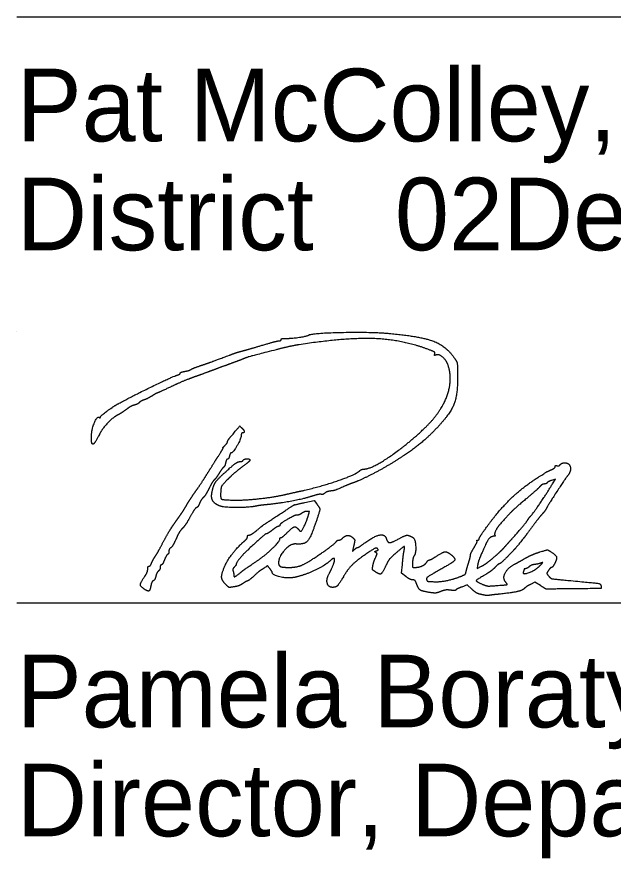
# Model space of a CAD drawing. Extents: x 36.7 to 70.7, y 0 to 22.
# Drawn here: x 61.221 to 62.37, y 7.302 to 8.923 of the extents above; entities that cross this region are included whole.
import ezdxf

# ---------------------------------------------------------------- set-up
doc = ezdxf.new("R2010")
doc.units = 0
for name, color, linetype in [('Default', 7, 'Continuous'), ('SH_Data', 7, 'Continuous'), ('SH_Text', 7, 'Continuous')]:
    doc.layers.add(name, color=color, linetype=linetype)

msp = doc.modelspace()

# ---------------------------------------------------------------- linework, layer by layer
at = {"layer": 'Default'}
for points in [[(62.2531, 8.0232), (62.2585, 8.0321), (62.2511, 8.0296)], [(61.7758, 7.987), (61.7938, 7.9911), (61.7985, 7.9849)], [(61.9707, 7.8442), (61.9624, 7.8506), (61.9639, 7.8676)], [(62.1087, 7.8662), (62.1077, 7.8597), (62.1163, 7.8642)], [(62.2296, 7.8269), (62.2189, 7.8337), (62.2105, 7.8292)], [(62.0977, 7.8199), (62.0885, 7.8282), (62.078, 7.8241)]]:
    msp.add_lwpolyline(points, dxfattribs=at)
for points in [[(61.7302, 8.3012), (61.7302, 8.3025), (61.7342, 8.3035), (61.7392, 8.3034)], [(61.7392, 8.3034), (61.7488, 8.3031), (61.7798, 8.3075), (61.7832, 8.3096)], [(62.0139, 8.282), (61.9633, 8.301), (61.8553, 8.3049), (61.765, 8.2912)], [(61.7832, 8.3096), (61.79, 8.3138), (61.907, 8.3161), (61.9414, 8.3127)], [(61.9414, 8.3127), (62.0007, 8.3069), (62.0482, 8.2886), (62.064, 8.2655)], [(61.6546, 8.2789), (61.6599, 8.2802), (61.6774, 8.2853), (61.6934, 8.29)], [(61.6934, 8.29), (61.7095, 8.2948), (61.7244, 8.2987), (61.7264, 8.2987)], [(61.765, 8.2912), (61.7558, 8.2898), (61.7358, 8.2854), (61.7206, 8.2815)], [(61.7264, 8.2987), (61.7285, 8.2987), (61.7302, 8.2998), (61.7302, 8.3012)], [(61.5742, 8.2505), (61.5889, 8.2555), (61.5954, 8.2579), (61.6306, 8.271)], [(61.6306, 8.271), (61.6385, 8.274), (61.6493, 8.2775), (61.6546, 8.2789)], [(61.7206, 8.2815), (61.6696, 8.2683), (61.6653, 8.267), (61.6546, 8.2627)], [(62.0262, 8.2733), (62.0272, 8.2758), (62.0237, 8.2783), (62.0139, 8.282)], [(62.0286, 8.2713), (62.026, 8.2703), (62.0253, 8.2709), (62.0262, 8.2733)], [(62.052, 8.2513), (62.0487, 8.2611), (62.0343, 8.2734), (62.0286, 8.2713)], [(61.6318, 8.2542), (61.6219, 8.2506), (61.6068, 8.245), (61.5982, 8.2418)], [(61.6546, 8.2627), (61.652, 8.2616), (61.6417, 8.2578), (61.6318, 8.2542)], [(62.064, 8.2655), (62.0689, 8.2583), (62.0698, 8.2539), (62.0702, 8.2361)], [(61.5358, 8.2362), (61.5358, 8.2373), (61.5398, 8.2389), (61.5448, 8.2398)], [(61.5448, 8.2398), (61.5497, 8.2407), (61.5549, 8.2423), (61.5562, 8.2433)], [(61.5562, 8.2433), (61.5575, 8.2443), (61.5656, 8.2475), (61.5742, 8.2505)], [(61.5982, 8.2418), (61.5896, 8.2386), (61.5734, 8.2326), (61.5622, 8.2287)], [(62.0065, 8.1302), (62.0374, 8.1596), (62.0613, 8.2231), (62.052, 8.2513)], [(61.4182, 8.1783), (61.4484, 8.1945), (61.522, 8.2302), (61.5304, 8.2326)], [(61.5622, 8.2287), (61.551, 8.2247), (61.5306, 8.2161), (61.517, 8.2096)], [(61.5304, 8.2326), (61.5334, 8.2335), (61.5358, 8.2351), (61.5358, 8.2362)], [(62.0702, 8.2361), (62.0709, 8.1953), (62.0548, 8.1556), (62.0254, 8.1257)], [(61.517, 8.2096), (61.5033, 8.2032), (61.4917, 8.1979), (61.4911, 8.1979)], [(61.4811, 8.1922), (61.4762, 8.1891), (61.4695, 8.1857), (61.4663, 8.1847)], [(61.4911, 8.1979), (61.4906, 8.1979), (61.4861, 8.1953), (61.4811, 8.1922)], [(61.3822, 8.1517), (61.3822, 8.1538), (61.4076, 8.1726), (61.4182, 8.1783)], [(61.4474, 8.1747), (61.4439, 8.1739), (61.4372, 8.1702), (61.4326, 8.1666)], [(61.4571, 8.1796), (61.4553, 8.1778), (61.451, 8.1756), (61.4474, 8.1747)], [(61.4663, 8.1847), (61.4631, 8.1837), (61.4589, 8.1814), (61.4571, 8.1796)], [(61.4326, 8.1666), (61.428, 8.1631), (61.4208, 8.1584), (61.4167, 8.1563)], [(61.365, 8.1138), (61.3651, 8.127), (61.3758, 8.1536), (61.3799, 8.151)], [(61.3799, 8.151), (61.3812, 8.1502), (61.3822, 8.1505), (61.3822, 8.1517)], [(61.4167, 8.1563), (61.4063, 8.151), (61.3864, 8.1301), (61.3802, 8.118)], [(61.6324, 8.1127), (61.6509, 8.1349), (61.6502, 8.1343), (61.6543, 8.1309)], [(61.6543, 8.1309), (61.6586, 8.1273), (61.6595, 8.1211), (61.6558, 8.1211)], [(61.8898, 8.0515), (61.9039, 8.0515), (61.972, 8.0974), (62.0065, 8.1302)], [(62.0254, 8.1257), (62.0068, 8.1068), (61.9744, 8.0819), (61.9439, 8.0631)], [(61.3664, 8.1001), (61.3656, 8.1009), (61.365, 8.107), (61.365, 8.1138)], [(61.3802, 8.118), (61.3735, 8.1051), (61.3682, 8.0982), (61.3664, 8.1001)], [(61.627, 8.1041), (61.627, 8.1053), (61.6294, 8.1092), (61.6324, 8.1127)], [(61.6534, 8.116), (61.6534, 8.1104), (61.6375, 8.0827), (61.6343, 8.0827)], [(61.6558, 8.1211), (61.6545, 8.1211), (61.6534, 8.1188), (61.6534, 8.116)], [(61.6094, 8.0766), (61.615, 8.0852), (61.619, 8.0923), (61.6184, 8.0923)], [(61.6184, 8.0923), (61.6179, 8.0923), (61.6196, 8.0944), (61.6222, 8.0971)], [(61.6222, 8.0971), (61.6248, 8.0997), (61.627, 8.1029), (61.627, 8.1041)], [(61.5874, 8.0416), (61.594, 8.0522), (61.6039, 8.068), (61.6094, 8.0766)], [(61.6308, 8.0767), (61.63, 8.0734), (61.6283, 8.0707), (61.6271, 8.0707)], [(61.6343, 8.0827), (61.6332, 8.0827), (61.6316, 8.08), (61.6308, 8.0767)], [(61.6186, 8.0417), (61.6343, 8.0563), (61.6471, 8.0659), (61.651, 8.0659)], [(61.6234, 8.0635), (61.6225, 8.0596), (61.6208, 8.0557), (61.6195, 8.0549)], [(61.6271, 8.0707), (61.6259, 8.0707), (61.6243, 8.0674), (61.6234, 8.0635)], [(61.651, 8.0659), (61.6535, 8.0659), (61.6562, 8.067), (61.657, 8.0683)], [(61.6702, 8.0686), (61.6702, 8.0675), (61.6634, 8.0616), (61.6552, 8.0555)], [(61.657, 8.0683), (61.6588, 8.0712), (61.6702, 8.0715), (61.6702, 8.0686)], [(61.9439, 8.0631), (61.9247, 8.0512), (61.8835, 8.0302), (61.8694, 8.0251)], [(62.2616, 8.0579), (62.2635, 8.0571), (62.2663, 8.0581), (62.2679, 8.06)], [(62.2679, 8.06), (62.2695, 8.0619), (62.2732, 8.0635), (62.2761, 8.0635)], [(62.2761, 8.0635), (62.2856, 8.0635), (62.2893, 8.0474), (62.2819, 8.0385)], [(61.611, 8.0435), (61.6076, 8.038), (61.6035, 8.0324), (61.6019, 8.031)], [(61.6195, 8.0549), (61.6182, 8.0541), (61.6144, 8.049), (61.611, 8.0435)], [(61.6552, 8.0555), (61.6469, 8.0494), (61.6344, 8.0386), (61.6274, 8.0314)], [(61.7698, 8.0095), (61.8067, 8.0177), (61.873, 8.0406), (61.8816, 8.0482)], [(61.8816, 8.0482), (61.8837, 8.05), (61.8874, 8.0515), (61.8898, 8.0515)], [(62.2214, 8.0331), (62.2404, 8.0453), (62.2422, 8.0464), (62.2504, 8.0501)], [(62.2504, 8.0501), (62.2547, 8.052), (62.2582, 8.0549), (62.2582, 8.0564)], [(62.2582, 8.0564), (62.2582, 8.0579), (62.2597, 8.0586), (62.2616, 8.0579)], [(61.5656, 8.0087), (61.571, 8.0161), (61.5808, 8.031), (61.5874, 8.0416)], [(61.6019, 8.031), (61.6002, 8.0297), (61.5955, 8.0221), (61.5915, 8.0141)], [(61.5973, 8.0071), (61.6, 8.0201), (61.6062, 8.0301), (61.6186, 8.0417)], [(61.6274, 8.0314), (61.6167, 8.0204), (61.6145, 8.0168), (61.614, 8.0085)], [(62.1268, 7.9406), (62.1491, 7.9714), (62.1941, 8.0154), (62.2214, 8.0331)], [(62.2819, 8.0385), (62.2777, 8.0334), (62.2449, 7.983), (62.2417, 7.9768)], [(62.2511, 8.0296), (62.2471, 8.0282), (62.2432, 8.026), (62.2424, 8.0248)], [(61.5915, 8.0141), (61.5875, 8.0061), (61.5824, 7.9981), (61.5802, 7.9963)], [(61.8538, 8.0189), (61.8367, 8.0115), (61.8318, 8.0098), (61.8252, 8.0091)], [(61.8694, 8.0251), (61.8648, 8.0235), (61.8577, 8.0207), (61.8538, 8.0189)], [(62.2283, 8.0173), (62.2256, 8.0143), (62.2131, 8.0032), (62.2006, 7.9927)], [(62.2103, 7.9603), (62.2131, 7.9622), (62.2413, 8.0037), (62.2531, 8.0232)], [(62.2371, 8.0227), (62.2349, 8.0227), (62.2309, 8.0202), (62.2283, 8.0173)], [(62.2424, 8.0248), (62.2417, 8.0236), (62.2393, 8.0227), (62.2371, 8.0227)], [(61.5489, 7.9831), (61.5528, 7.9897), (61.5603, 8.0012), (61.5656, 8.0087)], [(61.5802, 7.9963), (61.5781, 7.9945), (61.5748, 7.9895), (61.573, 7.9851)], [(61.6126, 7.9802), (61.6021, 7.9841), (61.595, 7.9966), (61.5973, 8.0071)], [(61.614, 8.0085), (61.6131, 7.9951), (61.6172, 7.9922), (61.6378, 7.9917)], [(61.6378, 7.9917), (61.657, 7.9911), (61.7149, 7.9972), (61.7362, 8.002)], [(61.7896, 7.9991), (61.7731, 7.9938), (61.728, 7.9853), (61.7042, 7.983)], [(61.7362, 8.002), (61.7441, 8.0038), (61.7592, 8.0072), (61.7698, 8.0095)], [(61.8076, 8.0028), (61.8059, 8.0034), (61.7978, 8.0017), (61.7896, 7.9991)], [(61.8144, 8.005), (61.8123, 8.0032), (61.8092, 8.0022), (61.8076, 8.0028)], [(61.8252, 8.0091), (61.8213, 8.0086), (61.8165, 8.0068), (61.8144, 8.005)], [(61.5359, 7.9624), (61.5392, 7.9672), (61.5451, 7.9765), (61.5489, 7.9831)], [(61.573, 7.9851), (61.5711, 7.9807), (61.5686, 7.9771), (61.5673, 7.9771)], [(61.6838, 7.9804), (61.6701, 7.9773), (61.6206, 7.9772), (61.6126, 7.9802)], [(61.7042, 7.983), (61.6959, 7.9822), (61.6867, 7.981), (61.6838, 7.9804)], [(61.7218, 7.9606), (61.7534, 7.9816), (61.7548, 7.9823), (61.7758, 7.987)], [(61.7985, 7.9849), (61.8051, 7.9762), (61.8049, 7.9713), (61.7972, 7.9487)], [(62.2006, 7.9927), (62.181, 7.9762), (62.1693, 7.9648), (62.1526, 7.9459)], [(61.5223, 7.9432), (61.5264, 7.949), (61.5325, 7.9577), (61.5359, 7.9624)], [(61.5673, 7.9771), (61.566, 7.9771), (61.5606, 7.9692), (61.5552, 7.9595)], [(61.7612, 7.9627), (61.759, 7.9627), (61.7546, 7.9613), (61.7515, 7.9595)], [(61.7699, 7.9662), (61.7674, 7.9643), (61.7634, 7.9627), (61.7612, 7.9627)], [(61.7684, 7.9315), (61.7702, 7.9315), (61.78, 7.9526), (61.7831, 7.9633)], [(61.7798, 7.9698), (61.7769, 7.9698), (61.7725, 7.9681), (61.7699, 7.9662)], [(61.7831, 7.9633), (61.7848, 7.9691), (61.7844, 7.9699), (61.7798, 7.9698)], [(62.2331, 7.9647), (62.2301, 7.9614), (62.2212, 7.9501), (62.2133, 7.9395)], [(62.2417, 7.9768), (62.24, 7.9733), (62.2361, 7.9679), (62.2331, 7.9647)], [(61.5552, 7.9595), (61.5499, 7.9499), (61.5432, 7.9399), (61.5404, 7.9373)], [(61.6826, 7.9327), (61.6963, 7.9438), (61.6943, 7.9424), (61.7218, 7.9606)], [(61.7515, 7.9595), (61.7371, 7.9516), (61.7278, 7.9452), (61.7278, 7.9432)], [(61.7972, 7.9487), (61.7869, 7.9188), (61.775, 7.9058), (61.759, 7.9071)], [(62.1751, 7.9173), (62.1904, 7.9344), (62.204, 7.9508), (62.2064, 7.9551)], [(62.2064, 7.9551), (62.2076, 7.9573), (62.2094, 7.9596), (62.2103, 7.9603)], [(61.5034, 7.9111), (61.5097, 7.923), (61.5182, 7.9374), (61.5223, 7.9432)], [(61.5404, 7.9373), (61.5375, 7.9348), (61.532, 7.9257), (61.5281, 7.9171)], [(61.6688, 7.9243), (61.6706, 7.9243), (61.6768, 7.9281), (61.6826, 7.9327)], [(61.7134, 7.9339), (61.7084, 7.9299), (61.7034, 7.9267), (61.7022, 7.9267)], [(61.7251, 7.9411), (61.7237, 7.9411), (61.7184, 7.9378), (61.7134, 7.9339)], [(61.7278, 7.9432), (61.7278, 7.942), (61.7266, 7.9411), (61.7251, 7.9411)], [(61.7422, 7.9291), (61.7523, 7.9392), (61.7589, 7.941), (61.7638, 7.9351)], [(61.7638, 7.9351), (61.7654, 7.9331), (61.7675, 7.9315), (61.7684, 7.9315)], [(62.1118, 7.9172), (62.1118, 7.9187), (62.1185, 7.9292), (62.1268, 7.9406)], [(62.1526, 7.9459), (62.1467, 7.9393), (62.1405, 7.9264), (62.1419, 7.9241)], [(62.2133, 7.9395), (62.2054, 7.9288), (62.1978, 7.9186), (62.1963, 7.9168)], [(61.5281, 7.9171), (61.5241, 7.9085), (61.5194, 7.9006), (61.5176, 7.8996)], [(61.66, 7.913), (61.6629, 7.9155), (61.6654, 7.919), (61.6654, 7.9208)], [(61.6654, 7.9208), (61.6654, 7.9227), (61.6669, 7.9243), (61.6688, 7.9243)], [(61.7022, 7.9267), (61.7004, 7.9266), (61.6919, 7.9194), (61.6666, 7.8961)], [(61.6817, 7.8729), (61.6973, 7.8833), (61.7278, 7.9121), (61.7278, 7.9163)], [(61.7278, 7.9163), (61.7278, 7.9181), (61.7289, 7.9195), (61.7302, 7.9195)], [(61.7302, 7.9195), (61.7315, 7.9195), (61.7369, 7.9238), (61.7422, 7.9291)], [(61.8365, 7.9116), (61.8376, 7.9133), (61.8399, 7.9147), (61.8417, 7.9147)], [(61.8417, 7.9147), (61.8436, 7.9147), (61.8468, 7.9164), (61.8489, 7.9186)], [(61.8489, 7.9186), (61.8539, 7.9235), (61.8639, 7.9236), (61.8688, 7.9187)], [(61.8688, 7.9187), (61.872, 7.9155), (61.8722, 7.913), (61.8701, 7.9039)], [(61.887, 7.906), (61.9072, 7.9212), (61.9299, 7.9268), (61.9329, 7.9173)], [(61.9329, 7.9173), (61.9353, 7.9097), (61.9434, 7.9096), (61.9567, 7.917)], [(61.9567, 7.917), (61.9686, 7.9236), (61.9759, 7.9243), (61.9841, 7.9197)], [(61.9841, 7.9197), (61.9885, 7.9173), (61.9902, 7.8892), (61.9863, 7.8841)], [(62.1076, 7.9132), (62.1068, 7.914), (62.1075, 7.9147), (62.109, 7.9147)], [(62.109, 7.9147), (62.1105, 7.9147), (62.1118, 7.9158), (62.1118, 7.9172)], [(62.1397, 7.9219), (62.1333, 7.9219), (62.1238, 7.9067), (62.1117, 7.8775)], [(62.1419, 7.9241), (62.1427, 7.9229), (62.1416, 7.9219), (62.1397, 7.9219)], [(62.1595, 7.8998), (62.1626, 7.9034), (62.1696, 7.9112), (62.1751, 7.9173)], [(62.1963, 7.9168), (62.183, 7.9004), (62.1785, 7.8952), (62.1666, 7.883)], [(61.488, 7.8835), (61.4902, 7.8868), (61.4972, 7.8992), (61.5034, 7.9111)], [(61.5176, 7.8996), (61.5157, 7.8985), (61.5142, 7.8956), (61.5142, 7.8931)], [(61.6219, 7.8648), (61.6264, 7.8753), (61.6496, 7.9047), (61.66, 7.913)], [(61.759, 7.9071), (61.7486, 7.908), (61.7254, 7.8826), (61.7254, 7.8704)], [(61.7938, 7.8798), (61.8124, 7.8922), (61.8348, 7.9088), (61.8365, 7.9116)], [(61.8701, 7.9039), (61.8678, 7.8936), (61.8679, 7.8931), (61.8717, 7.8966)], [(61.8717, 7.8966), (61.8739, 7.8986), (61.8766, 7.9003), (61.8775, 7.9003)], [(61.8775, 7.9003), (61.8785, 7.9003), (61.8827, 7.9028), (61.887, 7.906)], [(61.9156, 7.8982), (61.9138, 7.9), (61.9079, 7.8972), (61.8954, 7.8887)], [(61.914, 7.894), (61.917, 7.8952), (61.9174, 7.8964), (61.9156, 7.8982)], [(61.9668, 7.8925), (61.9687, 7.9019), (61.966, 7.9023), (61.9567, 7.8941)], [(62.095, 7.8856), (62.095, 7.8874), (62.0982, 7.8941), (62.102, 7.9004)], [(62.102, 7.9004), (62.1059, 7.9067), (62.1084, 7.9125), (62.1076, 7.9132)], [(62.1394, 7.881), (62.1473, 7.8878), (62.1564, 7.8963), (62.1595, 7.8998)], [(61.4811, 7.8709), (61.4827, 7.8745), (61.4858, 7.8802), (61.488, 7.8835)], [(61.5117, 7.887), (61.5103, 7.8862), (61.5075, 7.8812), (61.5054, 7.8761)], [(61.5142, 7.8931), (61.5142, 7.8906), (61.5131, 7.8879), (61.5117, 7.887)], [(61.6666, 7.8961), (61.6575, 7.8878), (61.6438, 7.8707), (61.6438, 7.8677)], [(61.8954, 7.8887), (61.8757, 7.8753), (61.8585, 7.8583), (61.8502, 7.8439)], [(61.9128, 7.8906), (61.9106, 7.8919), (61.9109, 7.8928), (61.914, 7.894)], [(61.9121, 7.8807), (61.915, 7.887), (61.9151, 7.8891), (61.9128, 7.8906)], [(61.9567, 7.8941), (61.9408, 7.8801), (61.9371, 7.8757), (61.9316, 7.8643)], [(61.9639, 7.8676), (61.9647, 7.877), (61.966, 7.8882), (61.9668, 7.8925)], [(61.9863, 7.8841), (61.985, 7.8824), (61.9837, 7.8767), (61.9833, 7.8715)], [(62.0158, 7.8763), (62.017, 7.8763), (62.0231, 7.8795), (62.0294, 7.8835)], [(62.0576, 7.8864), (62.0673, 7.8788), (62.0604, 7.8709), (62.0289, 7.8532)], [(62.0294, 7.8835), (62.0423, 7.8917), (62.0499, 7.8925), (62.0576, 7.8864)], [(62.0915, 7.8715), (62.0934, 7.8774), (62.095, 7.8838), (62.095, 7.8856)], [(62.1666, 7.883), (62.1591, 7.8754), (62.1521, 7.8691), (62.151, 7.8691)], [(62.1994, 7.879), (62.2073, 7.8835), (62.2205, 7.8892), (62.2287, 7.8917)], [(62.2287, 7.8917), (62.2427, 7.8959), (62.2439, 7.8959), (62.2498, 7.8921)], [(62.2498, 7.8921), (62.2594, 7.8858), (62.2618, 7.8784), (62.2572, 7.8694)], [(61.4758, 7.8643), (61.4772, 7.8643), (61.4796, 7.8672), (61.4811, 7.8709)], [(61.4995, 7.8667), (61.4984, 7.8667), (61.4974, 7.8646), (61.4974, 7.8622)], [(61.5054, 7.8761), (61.5034, 7.8709), (61.5007, 7.8667), (61.4995, 7.8667)], [(61.6438, 7.8677), (61.6438, 7.867), (61.6421, 7.8646), (61.6401, 7.8626)], [(61.6502, 7.8506), (61.6577, 7.8567), (61.663, 7.8604), (61.6817, 7.8729)], [(61.7088, 7.8593), (61.7043, 7.8651), (61.7043, 7.8651), (61.6975, 7.8607)], [(61.7254, 7.8704), (61.7254, 7.8652), (61.7332, 7.8619), (61.7453, 7.8619)], [(61.7453, 7.8619), (61.7584, 7.8619), (61.7775, 7.8689), (61.7938, 7.8798)], [(61.8258, 7.8756), (61.8162, 7.8665), (61.7774, 7.8477), (61.759, 7.8433)], [(61.8228, 7.8499), (61.8269, 7.8575), (61.8334, 7.8738), (61.8334, 7.8766)], [(61.8334, 7.8766), (61.8334, 7.8796), (61.8294, 7.8791), (61.8258, 7.8756)], [(61.9116, 7.8536), (61.9066, 7.8568), (61.9058, 7.8588), (61.907, 7.8651)], [(61.907, 7.8651), (61.9078, 7.8693), (61.9101, 7.8763), (61.9121, 7.8807)], [(61.9833, 7.8715), (61.9828, 7.8639), (61.9835, 7.8619), (61.9867, 7.8619)], [(61.9867, 7.8619), (61.995, 7.8619), (62.007, 7.8667), (62.0102, 7.8714)], [(62.0102, 7.8714), (62.0121, 7.8741), (62.0146, 7.8763), (62.0158, 7.8763)], [(62.0867, 7.8544), (62.0874, 7.8579), (62.0896, 7.8655), (62.0915, 7.8715)], [(62.1117, 7.8775), (62.1106, 7.8748), (62.1093, 7.8698), (62.1087, 7.8662)], [(62.1163, 7.8642), (62.1211, 7.8666), (62.1315, 7.8742), (62.1394, 7.881)], [(62.151, 7.8691), (62.1499, 7.8691), (62.146, 7.8659), (62.1424, 7.8621)], [(62.1628, 7.8336), (62.1567, 7.841), (62.1665, 7.8608), (62.1798, 7.868)], [(62.1798, 7.868), (62.1827, 7.8695), (62.1915, 7.8745), (62.1994, 7.879)], [(62.2188, 7.8676), (62.2149, 7.8671), (62.21, 7.8651), (62.2078, 7.8631)], [(62.2306, 7.8703), (62.228, 7.8693), (62.2226, 7.8681), (62.2188, 7.8676)], [(62.2282, 7.8648), (62.2337, 7.8704), (62.2343, 7.8717), (62.2306, 7.8703)], [(62.2572, 7.8694), (62.255, 7.8653), (62.2523, 7.8619), (62.2512, 7.8619)], [(61.4676, 7.8444), (61.4708, 7.8491), (61.4734, 7.8555), (61.4734, 7.8586)], [(61.4734, 7.8586), (61.4734, 7.8617), (61.4745, 7.8643), (61.4758, 7.8643)], [(61.4939, 7.8548), (61.4921, 7.8532), (61.4898, 7.8487), (61.4889, 7.8447)], [(61.4974, 7.8622), (61.4974, 7.8597), (61.4958, 7.8564), (61.4939, 7.8548)], [(61.6236, 7.8291), (61.616, 7.8367), (61.6154, 7.8495), (61.6219, 7.8648)], [(61.6401, 7.8626), (61.638, 7.8605), (61.6369, 7.8573), (61.6377, 7.8554)], [(61.6377, 7.8554), (61.6384, 7.8534), (61.639, 7.8503), (61.639, 7.8485)], [(61.639, 7.8485), (61.639, 7.8436), (61.6424, 7.8443), (61.6502, 7.8506)], [(61.6975, 7.8607), (61.6893, 7.8553), (61.6867, 7.8533), (61.6755, 7.8433)], [(61.7133, 7.8519), (61.7133, 7.8528), (61.7113, 7.8561), (61.7088, 7.8593)], [(61.759, 7.8433), (61.7461, 7.8402), (61.7135, 7.8464), (61.7133, 7.8519)], [(61.8295, 7.8235), (61.8211, 7.8235), (61.8171, 7.8393), (61.8228, 7.8499)], [(61.9316, 7.8643), (61.9249, 7.8506), (61.9201, 7.848), (61.9116, 7.8536)], [(62.0289, 7.8532), (62.0156, 7.8458), (62.0094, 7.8409), (62.0102, 7.8388)], [(62.074, 7.8438), (62.0828, 7.8471), (62.0858, 7.8496), (62.0867, 7.8544)], [(62.1424, 7.8621), (62.1388, 7.8583), (62.1307, 7.8522), (62.1244, 7.8485)], [(62.1968, 7.8537), (62.1943, 7.8472), (62.2197, 7.8562), (62.2282, 7.8648)], [(62.1982, 7.8585), (62.1982, 7.8579), (62.1975, 7.8558), (62.1968, 7.8537)], [(62.201, 7.8595), (62.1995, 7.8595), (62.1982, 7.859), (62.1982, 7.8585)], [(62.2078, 7.8631), (62.2056, 7.8611), (62.2025, 7.8595), (62.201, 7.8595)], [(62.2453, 7.8561), (62.2418, 7.8507), (62.2419, 7.8498), (62.2457, 7.8451)], [(62.2512, 7.8619), (62.2501, 7.8619), (62.2474, 7.8593), (62.2453, 7.8561)], [(61.4659, 7.8207), (61.4589, 7.8255), (61.4594, 7.8323), (61.4676, 7.8444)], [(61.4842, 7.8363), (61.4825, 7.8357), (61.4804, 7.8315), (61.4796, 7.8271)], [(61.4889, 7.8447), (61.488, 7.8408), (61.4859, 7.837), (61.4842, 7.8363)], [(61.6648, 7.8355), (61.6637, 7.8355), (61.6599, 7.8333), (61.6563, 7.8307)], [(61.6755, 7.8433), (61.6707, 7.839), (61.6659, 7.8355), (61.6648, 7.8355)], [(61.8502, 7.8439), (61.842, 7.8298), (61.8356, 7.8235), (61.8295, 7.8235)], [(61.9837, 7.8379), (61.9812, 7.8379), (61.9753, 7.8407), (61.9707, 7.8442)], [(61.9913, 7.8301), (61.9894, 7.8352), (61.9868, 7.8379), (61.9837, 7.8379)], [(62.0102, 7.8388), (62.0116, 7.8353), (62.0123, 7.8351), (62.0242, 7.8344)], [(62.0242, 7.8344), (62.0347, 7.8338), (62.0609, 7.8387), (62.074, 7.8438)], [(62.1244, 7.8485), (62.1065, 7.8381), (62.1055, 7.8348), (62.1184, 7.8293)], [(62.1452, 7.8269), (62.1647, 7.8284), (62.1665, 7.8291), (62.1628, 7.8336)], [(62.2457, 7.8451), (62.2493, 7.8406), (62.2543, 7.8396), (62.2882, 7.8364)], [(62.2882, 7.8364), (62.3373, 7.8319), (62.3456, 7.8304), (62.3465, 7.8256)], [(61.4796, 7.8271), (61.4777, 7.8174), (61.4735, 7.8154), (61.4659, 7.8207)], [(61.6398, 7.8245), (61.6311, 7.8231), (61.6289, 7.8237), (61.6236, 7.8291)], [(61.6563, 7.8307), (61.6527, 7.8281), (61.6453, 7.8253), (61.6398, 7.8245)], [(62.0166, 7.8136), (62.0016, 7.816), (61.9948, 7.8204), (61.9913, 7.8301)], [(62.0566, 7.818), (62.0508, 7.8188), (62.0435, 7.8178), (62.0377, 7.8155)], [(62.0667, 7.8184), (62.0663, 7.8175), (62.0617, 7.8173), (62.0566, 7.818)], [(62.078, 7.8241), (62.0721, 7.8218), (62.0671, 7.8193), (62.0667, 7.8184)], [(62.1123, 7.8104), (62.1093, 7.8111), (62.1027, 7.8153), (62.0977, 7.8199)], [(62.1184, 7.8293), (62.1252, 7.8264), (62.1317, 7.8258), (62.1452, 7.8269)], [(62.1988, 7.8213), (62.1951, 7.8176), (62.1736, 7.8127), (62.1502, 7.8103)], [(62.2105, 7.8292), (62.2059, 7.8267), (62.2006, 7.8232), (62.1988, 7.8213)], [(62.2762, 7.8205), (62.2405, 7.8201), (62.2401, 7.8201), (62.2296, 7.8269)], [(62.3465, 7.8256), (62.3473, 7.8213), (62.3453, 7.8212), (62.2762, 7.8205)], [(62.0377, 7.8155), (62.0307, 7.8127), (62.0252, 7.8122), (62.0166, 7.8136)], [(62.1226, 7.8083), (62.12, 7.8088), (62.1153, 7.8098), (62.1123, 7.8104)], [(62.131, 7.808), (62.129, 7.8076), (62.1252, 7.8077), (62.1226, 7.8083)], [(62.1502, 7.8103), (62.1416, 7.8095), (62.133, 7.8084), (62.131, 7.808)]]:
    msp.add_open_spline(points, degree=2, dxfattribs=at)
at = {"layer": 'SH_Data'}
for p, q in [((61.2213, 8.9231), (64.7213, 8.9231)), ((61.2213, 8.316), (61.2213, 8.316)), ((61.2213, 8.316), (61.2213, 8.316)), ((61.2213, 7.7937), (64.7213, 7.7937))]:
    msp.add_line(p, q, dxfattribs=at)

# ---------------------------------------------------------------- texts
at = {"layer": 'SH_Text'}
for s, p in [('Pat McColley, P.E., S.I.', (61.2213, 8.6832)), ('District       Deputy Director', (61.2213, 8.4732)), ('              02', (61.2213, 8.4732)), ('Pamela Boratyn', (61.2213, 7.5537)), ('Director, Department of Transportation', (61.2213, 7.3437))]:
    msp.add_text(s, height=0.14, dxfattribs=at).set_placement(p)

doc.saveas('drawing.dxf')
